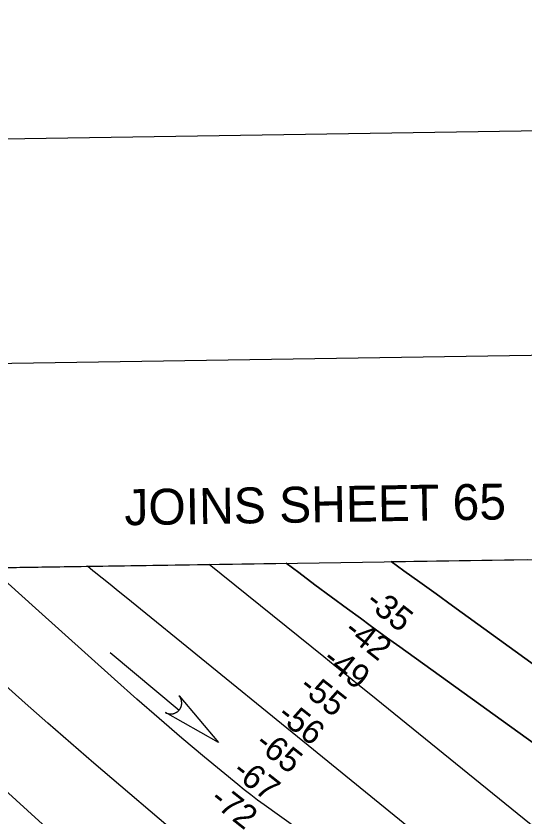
# Model space of a CAD drawing. Extents: x 3823584 to 3861785, y 301729 to 327625.
# Drawn here: x 3838628 to 3840042, y 324815 to 327042 of the extents above; entities that cross this region are included whole.
import ezdxf

# ---------------------------------------------------------------- set-up
doc = ezdxf.new("R2010")
doc.units = 0
for name, color, linetype in [('G-ANNO-NPLT', 7, 'Continuous'), ('V-ANNO-SYMB', 7, 'Continuous'), ('V-ANNO-TEXT', 7, 'Continuous'), ('V-GRID-FRAM', 7, 'Continuous'), ('V-RIVR-EDGE', 7, 'Continuous'), ('V-RIVR-RANG', 7, 'Continuous'), ('V-STRM-FLOW', 7, 'Continuous'), ('V-TOPO-DPTH', 7, 'Continuous'), ('V-TOPO-MAJR', 7, 'Continuous'), ('V-TOPO-MINR', 7, 'Continuous')]:
    doc.layers.add(name, color=color, linetype=linetype)

msp = doc.modelspace()

# ---------------------------------------------------------------- linework, layer by layer
at = {"layer": 'G-ANNO-NPLT'}
msp.add_lwpolyline([(3824539.5, 302312.7), (3861201.8, 302878), (3860829.2, 327041.8), (3824166.9, 326476.5)], close=True, dxfattribs=at)
at = {"layer": 'V-ANNO-SYMB'}
msp.add_lwpolyline([(3827279.7, 302980), (3860358.9, 303490.1), (3860005.6, 326403.9), (3826926.4, 325893.9), (3827279.7, 302980)], dxfattribs=at)
at = {"layer": 'V-GRID-FRAM'}
msp.add_lwpolyline([(3827552.2, 325336), (3859397.3, 325827), (3859685.5, 307646.8), (3827824.6, 307155.6), (3827552.2, 325336)], dxfattribs=at)
at = {"layer": 'V-RIVR-EDGE'}
msp.add_spline([(3836304.4, 325474.2), (3836346.4, 325438.3), (3836389.4, 325406.1), (3836417.6, 325385.4), (3836442.7, 325366.7), (3836470.2, 325340.9), (3836497.8, 325313.9), (3836554.9, 325258.4), (3836598.5, 325215.9), (3836636.4, 325181.1), (3836681.3, 325139.8), (3836737.1, 325093.4), (3836790.9, 325041.2), (3836840.3, 324993.5), (3836889.1, 324947.1), (3836934.6, 324907.1), (3836980.8, 324871), (3837015.5, 324849.1), (3837040.5, 324829.1), (3837085.4, 324787.2), (3837143.8, 324734.3), (3837181.6, 324700.8), (3837223.3, 324659.6), (3837272.1, 324619.6), (3837314.4, 324579.6), (3837346.4, 324546.8), (3837364.4, 324527.4), (3837395.8, 324500.4), (3837442, 324462.3), (3837492.7, 324423), (3837554.3, 324372.7), (3837573.6, 324361.1), (3837583.2, 324359.1), (3837596.7, 324352.6), (3837621.1, 324337.8), (3837648, 324319.7), (3837677.5, 324292), (3837718.6, 324249.5), (3837753.8, 324214.7), (3837781.4, 324188.9), (3837800, 324179.8), (3837820, 324170.8), (3837850.7, 324134.1), (3837874.4, 324110.2), (3837909.1, 324073.5), (3837941.8, 324040.6), (3837989.9, 323991.7), (3838022.6, 323960.7), (3838034.1, 323947.8), (3838046.3, 323933.7), (3838066.8, 323916.3), (3838089.9, 323892.4), (3838140.6, 323849.2), (3838186.1, 323811.2), (3838215.7, 323785.4), (3838265.7, 323736.4), (3838297.1, 323707.4), (3838336.9, 323671.9), (3838360, 323645.5), (3838385.6, 323627.5), (3838404.2, 323615.8), (3838421.6, 323601.7), (3838441.4, 323582.3), (3838460, 323567.5), (3838468.4, 323563.6), (3838484.4, 323555.2), (3838548.6, 323496.6), (3838595.4, 323464.3), (3838650, 323422.4), (3838701.3, 323379.8), (3838749.4, 323345.6), (3838798.2, 323317.9), (3838856.6, 323274.6), (3838933, 323221.7), (3838989.5, 323184.3), (3839037.6, 323150.1), (3839068.4, 323134.6), (3839093.4, 323105), (3839110.7, 323086.9), (3839122.9, 323081.1), (3839143.5, 323065.6), (3839172.3, 323044.4), (3839191, 323032.7), (3839216, 323016), (3839242.3, 323006.3), (3839316.8, 322969.4), (3839341.8, 322955.9), (3839371.4, 322944.2), (3839391.3, 322935.8), (3839417.6, 322920.3), (3839461.3, 322894.5), (3839483.7, 322873.2), (3839520.3, 322851.3), (3839555.6, 322828.7), (3839599.9, 322806.7), (3839718.7, 322751.1), (3839768.1, 322726.6), (3839807.9, 322705.9), (3839836.9, 322696.2), (3839865.1, 322680.7), (3839887.6, 322667.8), (3839924.2, 322652.3), (3839969.8, 322630.3), (3840004.4, 322612.2), (3840037.8, 322597.4), (3840085.4, 322579.9), (3840108.5, 322565.7), (3840121.9, 322548.9), (3840123.2, 322539.9), (3840122.5, 322533.5), (3840118, 322521.3), (3840112.8, 322514.2), (3840095.5, 322509.1), (3840089.7, 322509.2), (3840085.2, 322504.7), (3840084.5, 322498.2), (3840085.8, 322491.8), (3840130.7, 322467.3), (3840169.9, 322448.5), (3840197.5, 322439.5), (3840209.1, 322437.5), (3840231.6, 322441.3), (3840246.4, 322449), (3840266.3, 322458.6), (3840273.4, 322466.3), (3840278.6, 322471.4), (3840288.9, 322480.4), (3840296, 322484.9), (3840301.8, 322484.8), (3840308.2, 322484.8), (3840320.4, 322479), (3840324.9, 322470), (3840326.8, 322461.6), (3840338.3, 322450), (3840344.7, 322444.9), (3840366.6, 322437.7), (3840385.8, 322428.1), (3840421.8, 322409.3), (3840466.1, 322385.4), (3840492.4, 322368.7), (3840506.5, 322357), (3840533.5, 322340.3), (3840559.2, 322331.2), (3840587.4, 322322.1), (3840611.8, 322311.8), (3840642, 322296.3), (3840678.6, 322276.3), (3840712.6, 322255.6), (3840733.2, 322242.1), (3840784.5, 322210.4), (3840835.9, 322183.3), (3840892.4, 322153.6), (3840923.9, 322139.4), (3840950.8, 322127.1), (3840989.3, 322100), (3841017.6, 322082.6), (3841061.2, 322062.5), (3841092.7, 322044.4), (3841151.1, 322005.1), (3841210.8, 321964.4), (3841240.3, 321939.3), (3841300, 321894.8), (3841335.9, 321862.6), (3841374.4, 321823.9), (3841411.6, 321789.7), (3841444.9, 321758.1), (3841469.9, 321736.2), (3841482.1, 321724), (3841496.2, 321704.7), (3841509.1, 321694.3), (3841523.2, 321687.2), (3841573.9, 321660.7), (3841624, 321631.7), (3841667.6, 321606.5), (3841696.5, 321593.6), (3841738.3, 321575.5), (3841787.1, 321556.7), (3841816, 321552.1), (3841851.3, 321545), (3841886.7, 321533.3), (3841930.3, 321511.4), (3841950.2, 321498.5), (3841977.2, 321483), (3841998.4, 321476.5), (3842053, 321463.5), (3842082.5, 321456.3), (3842109.5, 321444.7), (3842146.1, 321427.3), (3842196.2, 321402.1), (3842241.1, 321374.9), (3842288.6, 321345.3), (3842321.4, 321327.2), (3842366.9, 321295.6), (3842395.2, 321280.1), (3842429.2, 321264.6), (3842452.4, 321258.7), (3842471, 321249.7)], degree=3, dxfattribs=at)
at = {"layer": 'V-STRM-FLOW'}
msp.add_line((3838889.5, 325269.6), (3839082.2, 325109.7), dxfattribs=at)
msp.add_lwpolyline([(3839082.1, 325148.8), (3839191.2, 325019.3), (3839043.8, 325102.6), (3839046.6, 325101.3), (3839049.3, 325100.2), (3839050.4, 325099.9), (3839051.4, 325099.6), (3839052.7, 325099.3), (3839053.9, 325099.1), (3839054.9, 325099), (3839056.4, 325098.8), (3839057.9, 325098.7), (3839058.8, 325098.7), (3839059.9, 325098.7), (3839061.4, 325098.8), (3839062.5, 325098.9), (3839063.7, 325099.1), (3839064.5, 325099.3), (3839065.4, 325099.5), (3839066.5, 325099.7), (3839067.4, 325100), (3839068.4, 325100.3), (3839069.2, 325100.5), (3839070.3, 325101), (3839071.4, 325101.5), (3839072.2, 325101.9), (3839073.2, 325102.4), (3839074, 325102.8), (3839074.8, 325103.3), (3839075.3, 325103.6), (3839076.2, 325104.2), (3839077, 325104.8), (3839077.8, 325105.4), (3839078.5, 325106), (3839079.2, 325106.6), (3839080, 325107.3), (3839080.5, 325107.9), (3839081.4, 325108.7), (3839082.2, 325109.7), (3839082.5, 325110.1), (3839082.9, 325110.6), (3839083.3, 325111.1), (3839083.7, 325111.7), (3839084.1, 325112.3), (3839084.5, 325112.8), (3839084.9, 325113.5), (3839085.2, 325114), (3839085.6, 325114.7), (3839085.9, 325115.4), (3839086.2, 325115.8), (3839086.7, 325117.1), (3839087, 325117.7), (3839087.2, 325118.2), (3839087.5, 325119), (3839087.7, 325119.6), (3839087.9, 325120.4), (3839088.2, 325121.2), (3839088.4, 325122), (3839088.5, 325122.7), (3839088.7, 325123.2), (3839088.8, 325124), (3839088.9, 325124.7), (3839089, 325125.4), (3839089.1, 325126.3), (3839089.2, 325127.1), (3839089.2, 325128.1), (3839089.2, 325128.8), (3839089.2, 325129.7), (3839089.2, 325130.5), (3839089.2, 325131.1), (3839089.1, 325131.8), (3839089, 325132.8), (3839089, 325132.9), (3839088.9, 325133.5), (3839088.9, 325134), (3839088.8, 325134.6), (3839088.6, 325135.5), (3839088.5, 325136.1), (3839088.3, 325136.7), (3839088.1, 325137.5), (3839087.9, 325138.2), (3839087.7, 325138.7), (3839087.5, 325139.4), (3839087.2, 325140.3), (3839086.9, 325140.9), (3839086.8, 325141.3), (3839086.6, 325141.7), (3839086.4, 325142.1), (3839086.1, 325142.7), (3839085.8, 325143.3), (3839085.5, 325143.9), (3839085.2, 325144.4), (3839084.8, 325145.1), (3839084.5, 325145.6), (3839084.1, 325146.2), (3839083.5, 325147), (3839083.1, 325147.5), (3839082.8, 325148), (3839082.5, 325148.3), (3839082.3, 325148.6)], close=True, dxfattribs=at)
at = {"layer": 'V-TOPO-DPTH'}
for p, q in [((3839672, 325522.9), (3840051.4, 325528.7)), ((3836528.1, 325474.4), (3839380.3, 325518.4))]:
    msp.add_line(p, q, dxfattribs=at)
for points in [[(3840175.2, 325159.7), (3839842.9, 325400.1), (3839797.8, 325432.7), (3839752.6, 325465.2), (3839707.4, 325497.6), (3839672, 325522.9)], [(3839672, 325522.9), (3839707.4, 325497.6), (3839752.6, 325465.2), (3839797.8, 325432.7), (3839842.9, 325400.1), (3840175.2, 325159.7)], [(3840071.1, 325015.4), (3839696.5, 325285.1), (3839669, 325305.1), (3839641.5, 325325), (3839614, 325345.1), (3839586.6, 325365.2), (3839550.7, 325391.6), (3839505.4, 325425), (3839460.2, 325458.6), (3839415.1, 325492.2), (3839380.3, 325518.4)], [(3839380.3, 325518.4), (3839415.1, 325492.2), (3839460.2, 325458.6), (3839505.4, 325425), (3839550.7, 325391.6), (3839586.6, 325365.2), (3839614, 325345.1), (3839641.5, 325325), (3839669, 325305.1), (3839696.5, 325285.1), (3840071.1, 325015.4)]]:
    msp.add_lwpolyline(points, dxfattribs=at)
at = {"layer": 'V-TOPO-MAJR'}
msp.add_lwpolyline([(3840111.2, 324749.9), (3839610.8, 325155.6), (3839579.2, 325181.1), (3839547.7, 325206.7), (3839516.1, 325232.2), (3839484.5, 325257.7), (3839165.3, 325515.1)], dxfattribs=at)
at = {"layer": 'V-TOPO-MINR'}
for points in [[(3840175.2, 325159.7), (3839842.9, 325400.1), (3839797.8, 325432.7), (3839752.6, 325465.2), (3839707.4, 325497.6), (3839672, 325522.9)], [(3838911.3, 324600.9), (3838343.8, 325116.9), (3838333.2, 325126.6), (3838322.7, 325136.3), (3838312.2, 325146.2), (3838301.8, 325156), (3838236.8, 325217.8), (3838194, 325258.6), (3838151.3, 325299.6), (3838108.7, 325340.6), (3838066.2, 325381.8), (3837948.3, 325496.3)], [(3839101.2, 324742.9), (3838844.5, 324961.8), (3838780.3, 325017.1), (3838716.4, 325072.7), (3838653, 325128.9), (3838590, 325185.5), (3838473.7, 325290.9), (3838469.1, 325295.1), (3838464.4, 325299.3), (3838459.8, 325303.6), (3838455.2, 325307.8), (3838422.2, 325338.5), (3838401.1, 325358.2), (3838380.1, 325377.9), (3838359.3, 325397.8), (3838338.5, 325417.8), (3838252.3, 325501)], [(3839686.3, 324582.3), (3839318.7, 324845.4), (3839299.9, 324859.1), (3839281.4, 324873.1), (3839263.2, 324887.5), (3839245.1, 324902.1), (3839153, 324978.4), (3839089.4, 325031.7), (3839026.3, 325085.6), (3838963.8, 325140.2), (3838901.7, 325195.3), (3838682, 325393), (3838643.8, 325427.4), (3838605.6, 325461.7), (3838567.5, 325496), (3838556.7, 325505.7)], [(3840741.4, 324140.7), (3840037.8, 324532.5), (3840029.1, 324538.5), (3840020.5, 324544.7), (3840012.1, 324551.1), (3839939.1, 324608.4), (3839894.3, 324643.8), (3839849.7, 324679.2), (3839805.3, 324714.9), (3839760.9, 324750.8), (3839441, 325010.8), (3839426.2, 325022.8), (3839411.4, 325034.8), (3839396.7, 325046.9), (3839381.9, 325058.9), (3838934.4, 325422.9), (3838912.3, 325440.8), (3838890.2, 325458.7), (3838868, 325476.5), (3838845.8, 325494.3), (3838841.6, 325497.6), (3838826.4, 325509.8)], [(3840071.1, 325015.4), (3839696.5, 325285.1), (3839669, 325305.1), (3839641.5, 325325), (3839614, 325345.1), (3839586.6, 325365.2), (3839550.7, 325391.6), (3839505.4, 325425), (3839460.2, 325458.6), (3839415.1, 325492.2), (3839380.3, 325518.4)]]:
    msp.add_lwpolyline(points, dxfattribs=at)

# ---------------------------------------------------------------- texts
at = {"layer": 'V-ANNO-TEXT'}
msp.add_text('JOINS SHEET 65', height=100, rotation=0.8834, dxfattribs=at).set_placement((3838930.2, 325623.9))
at = {"layer": 'V-RIVR-RANG'}
for s, p in [('-35', (3839597.2, 325403.6)), ('-42', (3839537.1, 325323.6)), ('-49', (3839477.3, 325243.5)), ('-55', (3839412.1, 325167.5)), ('-56', (3839351.2, 325088.2)), ('-65', (3839289.5, 325009.5)), ('-67', (3839226.5, 324931.8)), ('-72', (3839164, 324853.8))]:
    msp.add_text(s, height=67, rotation=321.735, dxfattribs=at).set_placement(p)

doc.saveas('drawing.dxf')
